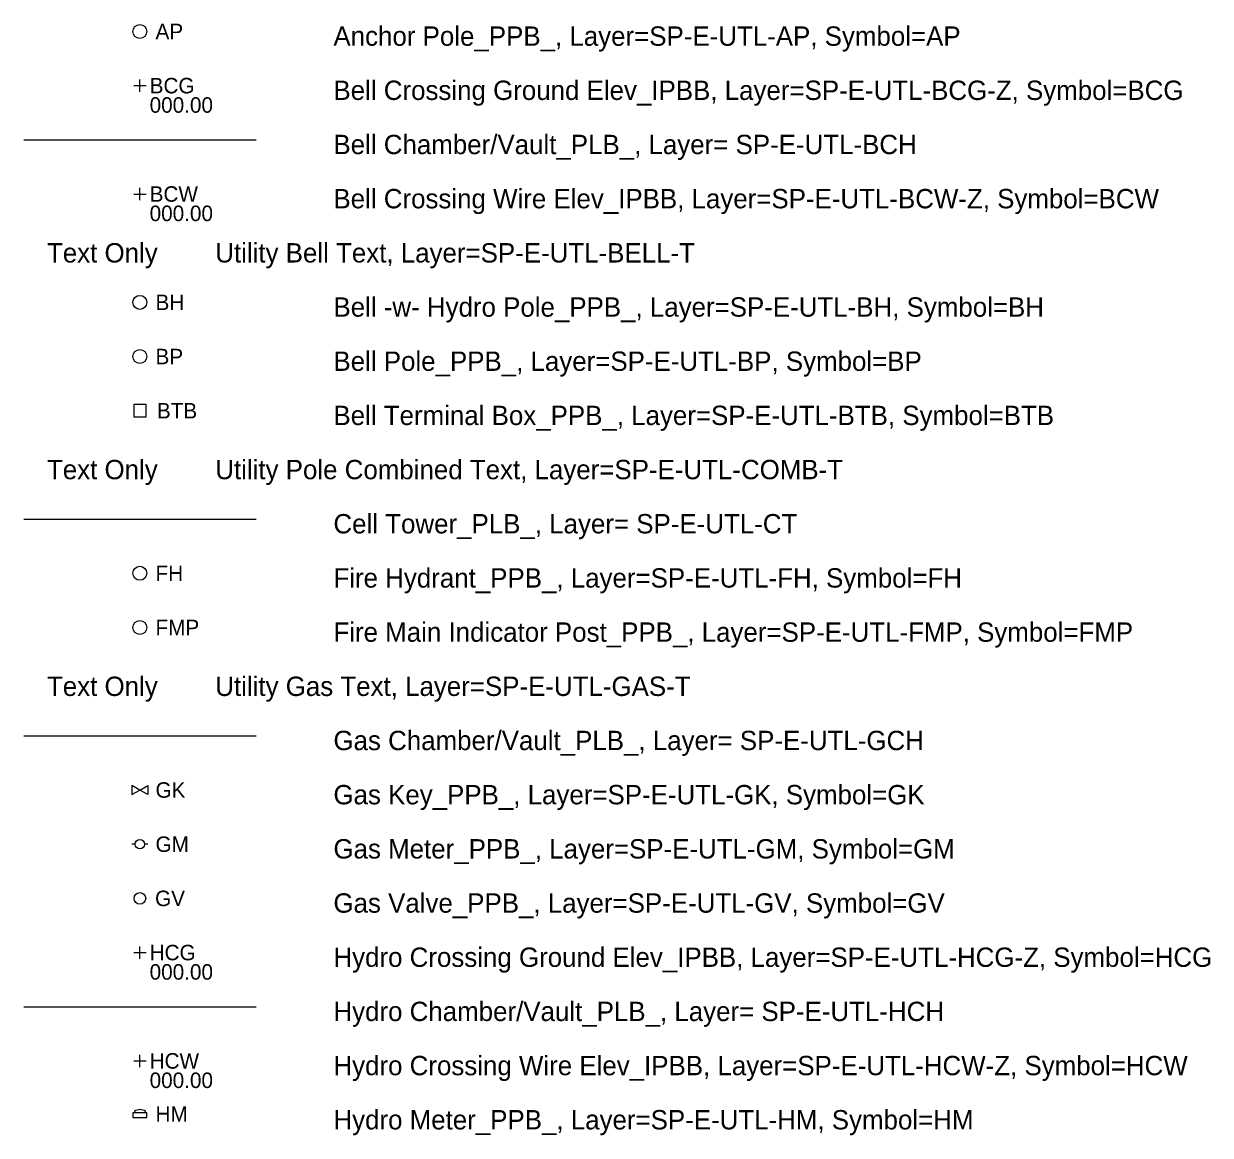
# Model space of a CAD drawing. Extents: x 500528 to 502626, y 4210261 to 4212624.
# Drawn here: x 500886.5 to 501039.8, y 4211000 to 4211143.6 of the extents above; entities that cross this region are included whole.
import ezdxf

# ---------------------------------------------------------------- set-up
doc = ezdxf.new("R2010")
doc.units = 0
for name, color, linetype in [('SP-E-UTL-AP', 7, 'Continuous'), ('SP-E-UTL-BCG-Z', 7, 'Continuous'), ('SP-E-UTL-BCH', 7, 'Continuous'), ('SP-E-UTL-BCW-Z', 7, 'Continuous'), ('SP-E-UTL-BELL-T', 7, 'Continuous'), ('SP-E-UTL-BH', 7, 'Continuous'), ('SP-E-UTL-BP', 7, 'Continuous'), ('SP-E-UTL-BTB', 7, 'Continuous'), ('SP-E-UTL-COMB-T', 7, 'Continuous'), ('SP-E-UTL-CT', 7, 'Continuous'), ('SP-E-UTL-FH', 7, 'Continuous'), ('SP-E-UTL-FMP', 7, 'Continuous'), ('SP-E-UTL-GAS-T', 7, 'Continuous'), ('SP-E-UTL-GCH', 7, 'Continuous'), ('SP-E-UTL-GK', 7, 'Continuous'), ('SP-E-UTL-GM', 7, 'Continuous'), ('SP-E-UTL-GV', 7, 'Continuous'), ('SP-E-UTL-HCG-Z', 7, 'Continuous'), ('SP-E-UTL-HCH', 7, 'Continuous'), ('SP-E-UTL-HCW-Z', 7, 'Continuous'), ('SP-E-UTL-HM', 7, 'Continuous'), ('SP-E-UTL-HYDRO-T', 7, 'Continuous'), ('SP-E-UTL-T', 7, 'Continuous')]:
    doc.layers.add(name, color=color, linetype=linetype)

# ---------------------------------------------------------------- blocks, each defined once
blk = doc.blocks.new('AP')
at = {"layer": 'SP-E-UTL-AP'}
blk.add_lwpolyline([(0, 0), (0, 0)], dxfattribs=at)
blk.add_circle((0, 0), 0.09, dxfattribs=at)
at = {"layer": 'SP-E-UTL-T'}
blk.add_text('AP', height=0.2, dxfattribs=at).set_placement((0.202, -0.1))
blk = doc.blocks.new('BCG')
at = {"layer": 'SP-E-UTL-BCG-Z'}
for points in [[(-0.08, 0), (0.08, 0)], [(0, -0.08), (0, 0.08)]]:
    blk.add_lwpolyline(points, dxfattribs=at)
at = {"layer": 'SP-E-UTL-BELL-T'}
for s, p in [('BCG', (0.126, -0.1)), ('000.00', (0.126, -0.35))]:
    blk.add_text(s, height=0.2, dxfattribs=at).set_placement(p)
blk = doc.blocks.new('BCW')
at = {"layer": 'SP-E-UTL-BCW-Z'}
for points in [[(-0.08, 0), (0.08, 0)], [(0, -0.08), (0, 0.08)]]:
    blk.add_lwpolyline(points, dxfattribs=at)
at = {"layer": 'SP-E-UTL-BELL-T'}
for s, p in [('BCW', (0.126, -0.1)), ('000.00', (0.126, -0.35))]:
    blk.add_text(s, height=0.2, dxfattribs=at).set_placement(p)
blk = doc.blocks.new('BH')
at = {"layer": 'SP-E-UTL-BH'}
blk.add_lwpolyline([(0, 0), (0, 0)], dxfattribs=at)
blk.add_circle((0, 0), 0.09, dxfattribs=at)
at = {"layer": 'SP-E-UTL-COMB-T'}
blk.add_text('BH', height=0.2, dxfattribs=at).set_placement((0.202, -0.1))
blk = doc.blocks.new('BP')
at = {"layer": 'SP-E-UTL-BP'}
blk.add_lwpolyline([(0, 0), (0, 0)], dxfattribs=at)
blk.add_circle((0, 0), 0.09, dxfattribs=at)
at = {"layer": 'SP-E-UTL-BELL-T'}
blk.add_text('BP', height=0.2, dxfattribs=at).set_placement((0.202, -0.1))
blk = doc.blocks.new('BTB')
at = {"layer": 'SP-E-UTL-BTB'}
for points in [[(-0.08, 0.08), (-0.08, -0.08), (0.08, -0.08), (0.08, 0.08), (-0.08, 0.08)], [(0, 0), (0, 0)]]:
    blk.add_lwpolyline(points, dxfattribs=at)
at = {"layer": 'SP-E-UTL-BELL-T'}
blk.add_text('BTB', height=0.2, dxfattribs=at).set_placement((0.22, -0.1))
blk = doc.blocks.new('FH')
at = {"layer": 'SP-E-UTL-FH'}
blk.add_lwpolyline([(0, 0), (0, 0)], dxfattribs=at)
blk.add_circle((0, 0), 0.09, dxfattribs=at)
at = {"layer": 'SP-E-UTL-T'}
blk.add_text('FH', height=0.2, dxfattribs=at).set_placement((0.202, -0.1))
blk = doc.blocks.new('FMP')
at = {"layer": 'SP-E-UTL-FMP'}
blk.add_lwpolyline([(0, 0), (0, 0)], dxfattribs=at)
blk.add_circle((0, 0), 0.09, dxfattribs=at)
at = {"layer": 'SP-E-UTL-T'}
blk.add_text('FMP', height=0.2, dxfattribs=at).set_placement((0.202, -0.1))
blk = doc.blocks.new('GK')
at = {"layer": 'SP-E-UTL-GK'}
for points in [[(-0.104, 0.06), (-0.104, -0.06), (0, 0), (-0.104, 0.06)], [(0.104, 0.06), (0.104, -0.06), (0, 0), (0.104, 0.06)]]:
    blk.add_lwpolyline(points, dxfattribs=at)
at = {"layer": 'SP-E-UTL-GAS-T'}
blk.add_text('GK', height=0.2, dxfattribs=at).set_placement((0.202, -0.1))
blk = doc.blocks.new('GM')
at = {"layer": 'SP-E-UTL-GM'}
for p, q in [((-0.06, 0), (-0.104, 0)), ((0.104, 0), (0.06, 0))]:
    blk.add_line(p, q, dxfattribs=at)
blk.add_circle((0, 0), 0.06, dxfattribs=at)
at = {"layer": 'SP-E-UTL-GAS-T'}
blk.add_text('GM', height=0.2, dxfattribs=at).set_placement((0.202, -0.1))
blk = doc.blocks.new('GV')
at = {"layer": 'SP-E-UTL-GV'}
blk.add_lwpolyline([(0, 0), (0, 0)], dxfattribs=at)
blk.add_circle((0, 0), 0.075, dxfattribs=at)
at = {"layer": 'SP-E-UTL-GAS-T'}
blk.add_text('GV', height=0.2, dxfattribs=at).set_placement((0.196, -0.1))
blk = doc.blocks.new('HCG')
at = {"layer": 'SP-E-UTL-HCG-Z'}
for points in [[(-0.08, 0), (0.08, 0)], [(0, -0.08), (0, 0.08)]]:
    blk.add_lwpolyline(points, dxfattribs=at)
at = {"layer": 'SP-E-UTL-HYDRO-T'}
for s, p in [('HCG', (0.126, -0.1)), ('000.00', (0.126, -0.35))]:
    blk.add_text(s, height=0.2, dxfattribs=at).set_placement(p)
blk = doc.blocks.new('HCW')
at = {"layer": 'SP-E-UTL-HCW-Z'}
for points in [[(-0.08, 0), (0.08, 0)], [(0, -0.08), (0, 0.08)]]:
    blk.add_lwpolyline(points, dxfattribs=at)
at = {"layer": 'SP-E-UTL-HYDRO-T'}
for s, p in [('HCW', (0.126, -0.1)), ('000.00', (0.126, -0.35))]:
    blk.add_text(s, height=0.2, dxfattribs=at).set_placement(p)
blk = doc.blocks.new('HM')
at = {"layer": 'SP-E-UTL-HM'}
for p, q in [((-0.071, 0.048), (-0.071, 0.031)), ((0.071, 0.031), (0.071, 0.048))]:
    blk.add_line(p, q, dxfattribs=at)
blk.add_lwpolyline([(-0.09, -0.031), (0.09, -0.031), (0.09, 0.031), (-0.09, 0.031)], close=True, dxfattribs=at)
blk.add_arc((0, -0.049), 0.12, 53.7956, 126.2044, dxfattribs=at)
at = {"layer": 'SP-E-UTL-HYDRO-T'}
blk.add_text('HM', height=0.2, dxfattribs=at).set_placement((0.202, -0.086))

msp = doc.modelspace()

# ---------------------------------------------------------------- linework, layer by layer
at = {"layer": 'SP-E-UTL-BCH'}
msp.add_line((500886.55, 4211128.59), (500916.55, 4211128.59), dxfattribs=at)
at = {"layer": 'SP-E-UTL-CT'}
msp.add_line((500886.55, 4211079.59), (500916.55, 4211079.59), dxfattribs=at)
at = {"layer": 'SP-E-UTL-GCH'}
msp.add_line((500886.55, 4211051.59), (500916.55, 4211051.59), dxfattribs=at)
at = {"layer": 'SP-E-UTL-HCH'}
msp.add_line((500886.55, 4211016.59), (500916.55, 4211016.59), dxfattribs=at)

# ---------------------------------------------------------------- block references
at = {"layer": 'SP-E-UTL-AP', "xscale": 10, "yscale": 10}
msp.add_blockref('AP', (500901.55, 4211142.59), dxfattribs=at)
at = {"layer": 'SP-E-UTL-BCG-Z', "xscale": 10, "yscale": 10}
msp.add_blockref('BCG', (500901.55, 4211135.59), dxfattribs=at)
at = {"layer": 'SP-E-UTL-BCW-Z', "xscale": 10, "yscale": 10}
msp.add_blockref('BCW', (500901.55, 4211121.59), dxfattribs=at)
at = {"layer": 'SP-E-UTL-BH', "xscale": 10, "yscale": 10}
msp.add_blockref('BH', (500901.55, 4211107.59), dxfattribs=at)
at = {"layer": 'SP-E-UTL-BP', "xscale": 10, "yscale": 10}
msp.add_blockref('BP', (500901.55, 4211100.59), dxfattribs=at)
at = {"layer": 'SP-E-UTL-BTB', "xscale": 10, "yscale": 10}
msp.add_blockref('BTB', (500901.55, 4211093.59), dxfattribs=at)
at = {"layer": 'SP-E-UTL-FH', "xscale": 10, "yscale": 10}
msp.add_blockref('FH', (500901.55, 4211072.59), dxfattribs=at)
at = {"layer": 'SP-E-UTL-FMP', "xscale": 10, "yscale": 10}
msp.add_blockref('FMP', (500901.55, 4211065.59), dxfattribs=at)
at = {"layer": 'SP-E-UTL-GK', "xscale": 10, "yscale": 10}
msp.add_blockref('GK', (500901.55, 4211044.59), dxfattribs=at)
at = {"layer": 'SP-E-UTL-GM', "xscale": 10, "yscale": 10}
msp.add_blockref('GM', (500901.55, 4211037.59), dxfattribs=at)
at = {"layer": 'SP-E-UTL-GV', "xscale": 10, "yscale": 10}
msp.add_blockref('GV', (500901.55, 4211030.59), dxfattribs=at)
at = {"layer": 'SP-E-UTL-HCG-Z', "xscale": 10, "yscale": 10}
msp.add_blockref('HCG', (500901.55, 4211023.59), dxfattribs=at)
at = {"layer": 'SP-E-UTL-HCW-Z', "xscale": 10, "yscale": 10}
msp.add_blockref('HCW', (500901.55, 4211009.59), dxfattribs=at)
at = {"layer": 'SP-E-UTL-HM', "xscale": 10, "yscale": 10}
msp.add_blockref('HM', (500901.55, 4211002.59), dxfattribs=at)

# ---------------------------------------------------------------- texts
at = {"layer": 'SP-E-UTL-AP'}
msp.add_text('Anchor Pole_PPB_, Layer=SP-E-UTL-AP, Symbol=AP ', height=2.5, dxfattribs=at).set_placement((500926.55, 4211140.74))
at = {"layer": 'SP-E-UTL-BCG-Z'}
msp.add_text('Bell Crossing Ground Elev_IPBB, Layer=SP-E-UTL-BCG-Z, Symbol=BCG ', height=2.5, dxfattribs=at).set_placement((500926.55, 4211133.74))
at = {"layer": 'SP-E-UTL-BCH'}
msp.add_text('Bell Chamber/Vault_PLB_, Layer= SP-E-UTL-BCH ', height=2.5, dxfattribs=at).set_placement((500926.55, 4211126.74))
at = {"layer": 'SP-E-UTL-BCW-Z'}
msp.add_text('Bell Crossing Wire Elev_IPBB, Layer=SP-E-UTL-BCW-Z, Symbol=BCW ', height=2.5, dxfattribs=at).set_placement((500926.55, 4211119.74))
at = {"layer": 'SP-E-UTL-BELL-T'}
msp.add_text('Text Only        Utility Bell Text, Layer=SP-E-UTL-BELL-T', height=2.5, dxfattribs=at).set_placement((500889.55, 4211112.74))
at = {"layer": 'SP-E-UTL-BH'}
msp.add_text('Bell -w- Hydro Pole_PPB_, Layer=SP-E-UTL-BH, Symbol=BH ', height=2.5, dxfattribs=at).set_placement((500926.55, 4211105.74))
at = {"layer": 'SP-E-UTL-BP'}
msp.add_text('Bell Pole_PPB_, Layer=SP-E-UTL-BP, Symbol=BP ', height=2.5, dxfattribs=at).set_placement((500926.55, 4211098.74))
at = {"layer": 'SP-E-UTL-BTB'}
msp.add_text('Bell Terminal Box_PPB_, Layer=SP-E-UTL-BTB, Symbol=BTB ', height=2.5, dxfattribs=at).set_placement((500926.55, 4211091.74))
at = {"layer": 'SP-E-UTL-COMB-T'}
msp.add_text('Text Only        Utility Pole Combined Text, Layer=SP-E-UTL-COMB-T', height=2.5, dxfattribs=at).set_placement((500889.55, 4211084.74))
at = {"layer": 'SP-E-UTL-CT'}
msp.add_text('Cell Tower_PLB_, Layer= SP-E-UTL-CT ', height=2.5, dxfattribs=at).set_placement((500926.55, 4211077.74))
at = {"layer": 'SP-E-UTL-FH'}
msp.add_text('Fire Hydrant_PPB_, Layer=SP-E-UTL-FH, Symbol=FH ', height=2.5, dxfattribs=at).set_placement((500926.55, 4211070.74))
at = {"layer": 'SP-E-UTL-FMP'}
msp.add_text('Fire Main Indicator Post_PPB_, Layer=SP-E-UTL-FMP, Symbol=FMP ', height=2.5, dxfattribs=at).set_placement((500926.55, 4211063.74))
at = {"layer": 'SP-E-UTL-GAS-T'}
msp.add_text('Text Only        Utility Gas Text, Layer=SP-E-UTL-GAS-T', height=2.5, dxfattribs=at).set_placement((500889.55, 4211056.74))
at = {"layer": 'SP-E-UTL-GCH'}
msp.add_text('Gas Chamber/Vault_PLB_, Layer= SP-E-UTL-GCH ', height=2.5, dxfattribs=at).set_placement((500926.55, 4211049.74))
at = {"layer": 'SP-E-UTL-GK'}
msp.add_text('Gas Key_PPB_, Layer=SP-E-UTL-GK, Symbol=GK ', height=2.5, dxfattribs=at).set_placement((500926.55, 4211042.74))
at = {"layer": 'SP-E-UTL-GM'}
msp.add_text('Gas Meter_PPB_, Layer=SP-E-UTL-GM, Symbol=GM ', height=2.5, dxfattribs=at).set_placement((500926.55, 4211035.74))
at = {"layer": 'SP-E-UTL-GV'}
msp.add_text('Gas Valve_PPB_, Layer=SP-E-UTL-GV, Symbol=GV ', height=2.5, dxfattribs=at).set_placement((500926.55, 4211028.74))
at = {"layer": 'SP-E-UTL-HCG-Z'}
msp.add_text('Hydro Crossing Ground Elev_IPBB, Layer=SP-E-UTL-HCG-Z, Symbol=HCG ', height=2.5, dxfattribs=at).set_placement((500926.55, 4211021.74))
at = {"layer": 'SP-E-UTL-HCH'}
msp.add_text('Hydro Chamber/Vault_PLB_, Layer= SP-E-UTL-HCH ', height=2.5, dxfattribs=at).set_placement((500926.55, 4211014.74))
at = {"layer": 'SP-E-UTL-HCW-Z'}
msp.add_text('Hydro Crossing Wire Elev_IPBB, Layer=SP-E-UTL-HCW-Z, Symbol=HCW ', height=2.5, dxfattribs=at).set_placement((500926.55, 4211007.74))
at = {"layer": 'SP-E-UTL-HM'}
msp.add_text('Hydro Meter_PPB_, Layer=SP-E-UTL-HM, Symbol=HM ', height=2.5, dxfattribs=at).set_placement((500926.55, 4211000.74))

doc.saveas('drawing.dxf')
